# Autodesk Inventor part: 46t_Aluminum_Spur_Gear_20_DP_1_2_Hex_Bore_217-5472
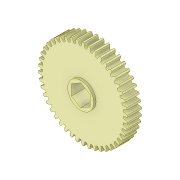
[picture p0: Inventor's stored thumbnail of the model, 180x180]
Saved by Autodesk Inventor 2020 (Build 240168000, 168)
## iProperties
Created: 2016-08
Part Number: 46t_Aluminum_Spur_Gear_20_DP_1_2_Hex_Bore_217-5472
Material: Aluminum 6061
Description: STEP AP214
Document SubType Name: Modeling
Designer: Kevin
Density: 2.7 g/cm^3
Appearance: Aluminum - Flat
Mass: 65.4301 g
Surface Area: 93.1994 cm^2
Volume: 24.2334 cm^3
Vendor: VEX
Sending System: SolidWorks 2015
Preprocessor: SwSTEP 2.0
Title: 217-5472-001 Rev1.STEP
Revision Number: ANY
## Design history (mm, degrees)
feature "Cut-Extrude1"
body "Solid1"
